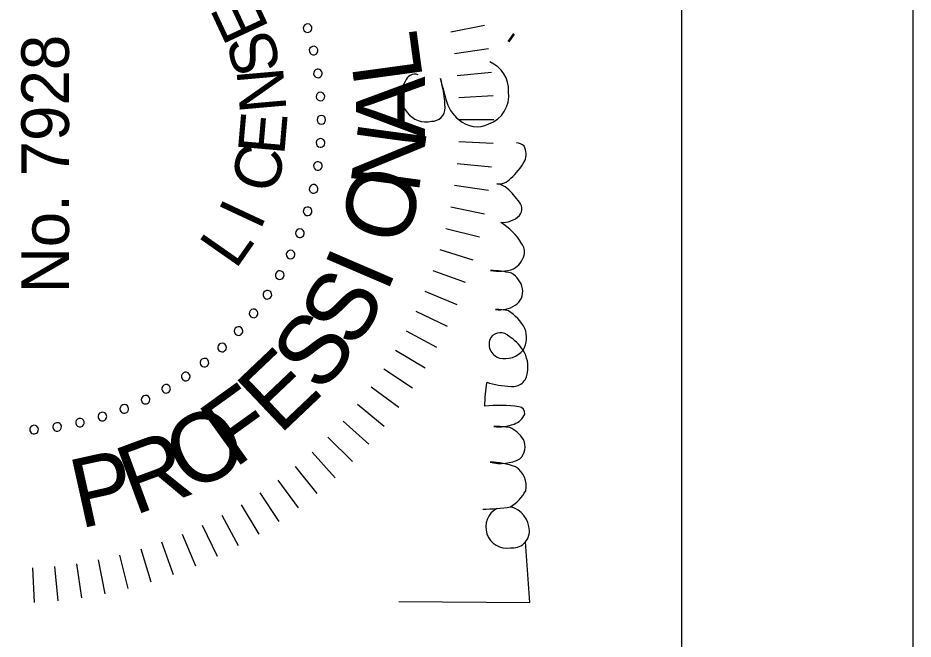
# Model space of a CAD drawing. Extents: x 916251 to 917164, y 328941 to 329491.
# Drawn here: x 917063.96 to 917100.87, y 329313.62 to 329339.21 of the extents above; entities that cross this region are included whole.
import ezdxf

# ---------------------------------------------------------------- set-up
doc = ezdxf.new("R2010")
doc.units = 0
for name, color, linetype in [('ANNOTATION', 7, 'Continuous'), ('Default', 7, 'Continuous'), ('elec-detail-ext-post-mtd-meter-panel', 7, 'Continuous')]:
    doc.layers.add(name, color=color, linetype=linetype)

# ---------------------------------------------------------------- blocks, each defined once
blk = doc.blocks.new('STAMP')
at = {"layer": 'Default'}
for p, q in [((-0.007955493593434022, 0.0011091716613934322), (-0.007387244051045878, 0.0011370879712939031)), ((-0.007926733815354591, 0.0007192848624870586), (-0.007360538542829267, 0.0007750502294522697)), ((-0.007878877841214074, 0.0003312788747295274), (-0.0073161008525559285, 0.00041475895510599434)), ((-0.007812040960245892, -5.391156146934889e-05), (-0.007254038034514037, 5.708212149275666e-05)), ((-0.0077263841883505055, -0.0004353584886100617), (-0.0071744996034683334, -0.00029711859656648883)), ((-0.007622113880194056, -0.0008121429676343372), (-0.007077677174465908, -0.0006469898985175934)), ((-0.00749948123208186, -0.0011833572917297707), (-0.0069638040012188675, -0.00099168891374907)), ((-0.007358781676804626, -0.0015481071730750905), (-0.006833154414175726, -0.001330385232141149)), ((-0.007200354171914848, -0.0019055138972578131), (-0.006686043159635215, -0.0016622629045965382)), ((-0.007024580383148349, -0.0022547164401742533), (-0.0065228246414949, -0.001986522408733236)), ((-0.006831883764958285, -0.002594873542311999), (-0.006343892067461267, -0.0023023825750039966)), ((-0.006622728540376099, -0.002925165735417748), (-0.0061496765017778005, -0.0026090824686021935)), ((-0.00639761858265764, -0.0032447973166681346), (-0.005940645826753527, -0.0029058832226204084)), ((-0.006157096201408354, -0.003552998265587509), (-0.005717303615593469, -0.0031920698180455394)), ((-0.005901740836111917, -0.003849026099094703), (-0.005480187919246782, -0.0034669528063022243)), ((-0.0056321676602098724, -0.0041321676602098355), (-0.00522986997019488, -0.003729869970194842)), ((-0.005349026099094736, -0.004401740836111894), (-0.004966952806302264, -0.003980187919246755)), ((-0.0050529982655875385, -0.004657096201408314), (-0.004692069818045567, -0.004217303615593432)), ((-0.004744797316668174, -0.0048976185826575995), (-0.004405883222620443, -0.004440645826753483)), ((-0.0044251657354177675, -0.005122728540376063), (-0.004109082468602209, -0.004649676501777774)), ((-0.004094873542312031, -0.005331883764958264), (-0.0038023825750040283, -0.004843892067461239)), ((-0.0037547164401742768, -0.005524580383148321), (-0.0034865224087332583, -0.005022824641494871)), ((-0.003405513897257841, -0.005700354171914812), (-0.0031622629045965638, -0.0051860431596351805)), ((-0.003048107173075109, -0.005858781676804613), (-0.0028303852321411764, -0.005333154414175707)), ((-0.0026833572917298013, -0.005999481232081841), (-0.002491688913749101, -0.005463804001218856)), ((-0.0023121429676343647, -0.006122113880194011), (-0.0021469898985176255, -0.005577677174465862)), ((-0.0019353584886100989, -0.006226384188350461), (-0.0017971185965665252, -0.005674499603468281)), ((-0.0015539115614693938, -0.006312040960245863), (-0.0014429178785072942, -0.005754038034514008)), ((0.0015539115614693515, -0.006312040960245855), (0.0014429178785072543, -0.005754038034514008)), ((-0.001168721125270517, -0.006378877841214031), (-0.0010852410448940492, -0.005816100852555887)), ((-0.0007807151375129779, -0.006426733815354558), (-0.0007249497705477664, -0.0058605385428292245)), ((-0.00039082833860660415, -0.006455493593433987), (-0.00036291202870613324, -0.005887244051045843)), ((-2.0539125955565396e-17, -0.006465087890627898), (-2.0539125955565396e-17, -0.005896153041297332)), ((0.0003908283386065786, -0.0064554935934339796), (0.0003629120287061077, -0.005887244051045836)), ((0.0007807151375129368, -0.006426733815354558), (0.0007249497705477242, -0.005860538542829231)), ((0.0011687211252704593, -0.006378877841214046), (0.0010852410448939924, -0.005816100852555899)), ((0.001282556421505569, -0.006716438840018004), (0.001411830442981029, -0.006805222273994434)), ((0.0012888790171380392, -0.0067038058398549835), (0.0014181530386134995, -0.006792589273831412))]:
    blk.add_line(p, q, dxfattribs=at)
blk.add_lwpolyline([(-0.007938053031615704, -0.004895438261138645), (-0.007956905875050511, -0.007061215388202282), (-0.0069577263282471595, -0.006985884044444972)], dxfattribs=at)
for centre, radius, start, end in [((-0.005106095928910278, 0.0011173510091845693), 7.111685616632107e-05, 94.28571428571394, 274.28571428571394), ((-0.005106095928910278, 0.0011173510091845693), 7.11168561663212e-05, 274.28571428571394, 94.28571428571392), ((-0.005063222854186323, 0.0007368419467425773), 7.111685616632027e-05, 98.5714285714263, 278.5714285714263), ((-0.005063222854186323, 0.0007368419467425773), 7.111685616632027e-05, 278.5714285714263, 98.5714285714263), ((-0.0049920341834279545, 0.00036060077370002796), 7.11168561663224e-05, 102.8571428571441, 282.8571428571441), ((-0.0049920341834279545, 0.00036060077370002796), 7.11168561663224e-05, 282.8571428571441, 102.85714285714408), ((-0.004892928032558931, -9.26841668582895e-06), 7.111685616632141e-05, 107.14285714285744, 287.14285714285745), ((-0.004892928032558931, -9.26841668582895e-06), 7.111685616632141e-05, 287.14285714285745, 107.14285714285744), ((-0.004766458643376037, -0.00037069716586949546), 7.111685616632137e-05, 111.42857142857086, 291.4285714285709), ((-0.004766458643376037, -0.00037069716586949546), 7.111685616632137e-05, 291.4285714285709, 111.42857142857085), ((-0.0046133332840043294, -0.0007216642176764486), 7.1116856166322e-05, 115.71428571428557, 295.71428571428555), ((-0.0046133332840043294, -0.0007216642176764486), 7.1116856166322e-05, 295.71428571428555, 115.71428571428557), ((-0.004434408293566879, -0.0010602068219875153), 7.111685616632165e-05, 119.99999999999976, 299.9999999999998), ((-0.004434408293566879, -0.0010602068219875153), 7.111685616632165e-05, 299.9999999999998, 119.99999999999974), ((-0.004230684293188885, -0.0013844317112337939), 7.111685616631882e-05, 124.28571428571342, 304.2857142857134), ((-0.004230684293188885, -0.0013844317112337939), 7.111685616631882e-05, 304.2857142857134, 124.28571428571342), ((-0.004003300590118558, -0.0016925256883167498), 7.111685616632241e-05, 308.5714285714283, 128.57142857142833), ((-0.004003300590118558, -0.0016925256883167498), 7.111685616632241e-05, 128.57142857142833, 308.5714285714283), ((-0.003753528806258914, -0.0019827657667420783), 7.11168561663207e-05, 312.85714285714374, 132.85714285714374), ((-0.003753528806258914, -0.0019827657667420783), 7.11168561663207e-05, 132.85714285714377, 312.8571428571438), ((-0.0034827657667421, -0.002253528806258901), 7.111685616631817e-05, 137.14285714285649, 317.1428571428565), ((-0.0034827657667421, -0.002253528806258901), 7.111685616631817e-05, 317.1428571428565, 137.14285714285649), ((-0.0031925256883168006, -0.0025033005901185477), 7.111685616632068e-05, 141.42857142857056, 321.42857142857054), ((-0.0031925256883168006, -0.0025033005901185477), 7.111685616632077e-05, 321.42857142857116, 141.4285714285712), ((-0.0028844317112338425, -0.0027306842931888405), 7.111685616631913e-05, 145.7142857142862, 325.71428571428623), ((-0.0028844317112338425, -0.0027306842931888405), 7.111685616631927e-05, 325.7142857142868, 145.71428571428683), ((-0.0025602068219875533, -0.0029344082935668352), 7.111685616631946e-05, 149.99999999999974, 329.9999999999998), ((-0.0025602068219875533, -0.0029344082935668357), 7.111685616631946e-05, 329.9999999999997, 149.99999999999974), ((-0.0022216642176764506, -0.0031133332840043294), 7.111685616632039e-05, 154.2857142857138, 334.28571428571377), ((-0.0022216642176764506, -0.0031133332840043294), 7.111685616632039e-05, 334.2857142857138, 154.2857142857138), ((-0.0018706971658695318, -0.003266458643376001), 7.111685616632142e-05, 158.57142857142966, 338.5714285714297), ((-0.0018706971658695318, -0.0032664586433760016), 7.111685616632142e-05, 338.57142857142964, 158.57142857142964), ((-0.0015092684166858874, -0.003392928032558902), 7.111685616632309e-05, 162.85714285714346, 342.85714285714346), ((-0.0015092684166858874, -0.003392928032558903), 7.111685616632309e-05, 342.85714285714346, 162.85714285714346), ((0.0015092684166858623, -0.0033929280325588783), 7.111685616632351e-05, 17.142857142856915, 197.1428571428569), ((0.0015092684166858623, -0.0033929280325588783), 7.111685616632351e-05, 197.1428571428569, 17.14285714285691), ((-0.0011393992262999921, -0.0034920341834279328), 7.111685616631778e-05, 167.14285714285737, 347.14285714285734), ((-0.0011393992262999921, -0.0034920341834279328), 7.111685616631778e-05, 347.14285714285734, 167.14285714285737), ((-0.0007631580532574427, -0.003563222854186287), 7.111685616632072e-05, 351.4285714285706, 171.4285714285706), ((-0.0003826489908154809, -0.003606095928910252), 7.111685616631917e-05, 355.7142857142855, 175.7142857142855), ((0.0003826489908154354, -0.0036060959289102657), 7.111685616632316e-05, 4.285714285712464, 184.28571428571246), ((0.0007631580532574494, -0.0035632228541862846), 7.111685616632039e-05, 8.571428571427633, 188.57142857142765), ((0.0011393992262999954, -0.0034920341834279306), 7.111685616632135e-05, 12.857142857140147, 192.85714285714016), ((0.0011393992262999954, -0.0034920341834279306), 7.111685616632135e-05, 192.85714285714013, 12.857142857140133), ((-0.0007631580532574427, -0.003563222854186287), 7.111685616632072e-05, 171.4285714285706, 351.4285714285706), ((-0.0003826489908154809, -0.003606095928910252), 7.111685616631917e-05, 175.71428571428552, 355.71428571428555), ((-1.2628786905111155e-17, -0.0036204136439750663), 7.111685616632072e-05, 0, 180), ((-1.2628786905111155e-17, -0.0036204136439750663), 7.111685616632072e-05, 180, 0), ((0.0003826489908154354, -0.0036060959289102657), 7.111685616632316e-05, 184.28571428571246, 4.285714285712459), ((0.0007631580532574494, -0.0035632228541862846), 7.111685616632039e-05, 188.57142857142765, 8.571428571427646), ((0.00039604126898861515, -0.005375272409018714), 0.00043958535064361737, 57.64755033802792, 128.97245422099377), ((0.0005805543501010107, -0.005165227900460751), 0.00016909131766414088, 342.3611945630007, 72.54487353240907), ((0.00036114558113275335, -0.0053488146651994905), 0.0003972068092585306, 127.45926190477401, 192.9614203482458), ((0.00019608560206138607, -0.005439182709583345), 0.0002220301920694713, 179.67057284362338, 269.694601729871), ((0.00015503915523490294, -0.003868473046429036), 0.001793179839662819, 271.2738092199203, 287.01217780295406), ((0.002166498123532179, -0.011827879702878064), 0.006419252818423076, 103.3923944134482, 106.55297850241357), ((0.0004564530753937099, -0.0062299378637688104), 0.0005678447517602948, 102.0773813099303, 143.39383108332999), ((0.00031613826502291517, -0.006186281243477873), 0.0004319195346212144, 136.9297266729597, 206.7934360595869), ((-0.00671307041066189, -0.006678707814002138), 0.0003465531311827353, 28.430349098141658, 189.68707560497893), ((-0.003955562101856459, -0.006312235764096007), 0.002461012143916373, 179.30402472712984, 190.0665804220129), ((-0.007015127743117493, -0.0065631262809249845), 0.0023079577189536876, 352.1195763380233, 6.249520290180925), ((-0.004786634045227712, -0.009314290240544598), 0.003003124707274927, 81.15725195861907, 88.74550427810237), ((-0.002857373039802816, -0.006810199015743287), 0.001539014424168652, 162.47862001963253, 177.5735090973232), ((-0.007040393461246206, -0.006369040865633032), 0.0013973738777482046, 341.03759348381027, 358.5906169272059), ((-0.004987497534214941, -0.006577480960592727), 0.0006786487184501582, 165.1377733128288, 207.96825790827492), ((-0.006329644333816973, -0.006519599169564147), 0.0012732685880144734, 350.5388137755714, 2.446920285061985), ((-0.004310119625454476, -0.006538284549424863), 0.0007509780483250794, 174.41813129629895, 200.30191948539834), ((-0.0037000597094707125, -0.006623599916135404), 0.00023723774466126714, 61.91684207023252, 163.66717131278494), ((-0.0037052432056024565, -0.0065716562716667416), 0.0001960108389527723, 312.7382758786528, 53.40100716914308), ((-0.003974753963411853, -0.006503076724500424), 0.0008496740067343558, 346.26214121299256, 0.7257075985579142), ((-0.002682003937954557, -0.006568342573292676), 0.00044961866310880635, 170.2648919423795, 213.2954708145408), ((-0.00388024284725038, -0.006412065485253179), 0.0013948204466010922, 345.72048696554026, 0.12433676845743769), ((-0.0016914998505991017, -0.006545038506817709), 0.0008054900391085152, 170.27954956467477, 197.78532003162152), ((0.0003962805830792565, -0.006217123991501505), 0.0004936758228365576, 199.38474076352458, 277.55079490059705), ((0.0004891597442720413, -0.006207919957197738), 0.0004993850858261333, 266.784921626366, 337.7362429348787), ((-0.0035430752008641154, -0.006644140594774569), 0.0003944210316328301, 167.2189950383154, 230.16055614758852), ((-0.002536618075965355, -0.006083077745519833), 0.0009765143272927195, 300.6803608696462, 329.51258202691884), ((-0.0012666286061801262, -0.006594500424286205), 0.00042878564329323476, 177.86300386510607, 223.17874837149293), ((-0.0013865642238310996, -0.006474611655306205), 0.0003320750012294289, 327.8843366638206, 353.1980671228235), ((-0.0008025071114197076, -0.006544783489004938), 0.0002561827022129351, 173.08541670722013, 230.55848375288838), ((-0.006777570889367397, -0.006772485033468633), 0.00027937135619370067, 172.70712454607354, 271.16395527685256), ((-0.006783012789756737, -0.006633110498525), 0.0004188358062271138, 271.5209447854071, 344.87406906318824), ((-0.005754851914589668, -0.006345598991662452), 0.0007393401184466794, 212.4592088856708, 240.63114206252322), ((-0.0055308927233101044, -0.006522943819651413), 0.0005014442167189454, 301.1133493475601, 335.74975916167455), ((-0.004152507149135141, -0.006775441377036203), 0.00024439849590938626, 172.85451562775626, 266.8151593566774), ((-0.00421927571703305, -0.006314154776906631), 0.0007614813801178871, 303.79189499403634, 328.18256979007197), ((-0.0038004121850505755, -0.006299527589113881), 0.000766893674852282, 298.0105046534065, 328.09350966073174), ((-0.00285343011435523, -0.006566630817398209), 0.0003761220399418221, 280.5798823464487, 329.7517392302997), ((-0.0020051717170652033, -0.0059200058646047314), 0.0011594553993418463, 305.5205731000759, 320.90595982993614), ((-0.0001785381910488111, -0.0060637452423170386), 0.0010391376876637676, 220.79179678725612, 241.16030041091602), ((-0.006036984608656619, -0.006622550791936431), 0.0003760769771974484, 257.6460165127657, 327.7710077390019), ((-0.005391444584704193, -0.006712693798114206), 0.0002677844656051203, 223.12676578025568, 296.5429712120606), ((-0.004715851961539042, -0.006689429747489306), 0.00031800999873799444, 200.1253724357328, 244.48124886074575), ((-0.004842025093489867, -0.006862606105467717), 0.00011432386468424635, 264.56536252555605, 351.47104640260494), ((-0.0028340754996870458, -0.006679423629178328), 0.00026169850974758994, 211.24435430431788, 280.94854976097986), ((-0.0021179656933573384, -0.00658432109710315), 0.00039838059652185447, 211.26450698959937, 253.32703764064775), ((-0.0021804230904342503, -0.006741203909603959), 0.00023065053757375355, 257.01114107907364, 308.02112433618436), ((-0.0014677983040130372, -0.006749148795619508), 0.0001780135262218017, 231.21384232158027, 319.94914487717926), ((-0.0005623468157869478, -0.006834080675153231), 0.00018159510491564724, 314.66347430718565, 358.2957841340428), ((-0.00407546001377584, -0.006500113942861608), 0.0005271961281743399, 260.1016649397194, 302.042575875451), ((-0.0035868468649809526, -0.00658750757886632), 0.00041578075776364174, 239.8376850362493, 290.64484911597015), ((-0.0005688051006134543, -0.006705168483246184), 0.00029083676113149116, 247.5695171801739, 297.4590386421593)]:
    blk.add_arc(centre, radius, start, end, dxfattribs=at)
for s, height, p in [('No. 7928', 0.0007851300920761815, (-0.002860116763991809, 0.0005420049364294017)), ('A', 0.0011378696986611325, (-0.0003007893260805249, -0.005327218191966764))]:
    blk.add_text(s, height=height, dxfattribs=at).set_placement(p)
for s, height, rotation, p in [('P', 0.0011378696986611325, 282.5, (-0.006741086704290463, 0.00036378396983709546)), ('R', 0.0011378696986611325, 290.25, (-0.00652629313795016, -0.0005348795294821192)), ('O', 0.0011378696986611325, 298, (-0.006169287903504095, -0.0014396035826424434)), ('F', 0.001137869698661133, 305.75, (-0.0057573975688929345, -0.002187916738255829)), ('L', 0.0007680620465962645, 324.99999999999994, (-0.002479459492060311, -0.00220631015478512)), ('E', 0.0007680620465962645, 25.000000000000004, (0.001513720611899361, -0.002766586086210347)), ('I', 0.0007680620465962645, 335, (-0.001841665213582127, -0.002604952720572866)), ('C', 0.0007680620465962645, 345, (-0.0012469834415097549, -0.0028524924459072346)), ('S', 0.0007680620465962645, 14.999999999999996, (0.0008506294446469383, -0.0029637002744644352)), ('E', 0.0011378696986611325, 313.5, (-0.005207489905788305, -0.0029306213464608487)), ('E', 0.0007680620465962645, 355, (-0.0005969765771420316, -0.00300722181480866)), ('N', 0.0007680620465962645, 5, (0.0001499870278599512, -0.003047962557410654)), ('S', 0.0011378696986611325, 321.25, (-0.004535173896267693, -0.0036142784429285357)), ('S', 0.0011378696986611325, 328.99999999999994, (-0.003804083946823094, -0.004179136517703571)), ('I', 0.0011378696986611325, 336.75, (-0.0028749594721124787, -0.00469547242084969)), ('O', 0.001137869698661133, 344.5, (-0.0021143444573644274, -0.004998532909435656)), ('N', 0.001137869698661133, 352.25, (-0.001239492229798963, -0.005221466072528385)), ('L', 0.001137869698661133, 7.75, (0.0006711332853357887, -0.0052988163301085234))]:
    blk.add_text(s, height=height, rotation=rotation, dxfattribs=at).set_placement(p)

msp = doc.modelspace()

# ---------------------------------------------------------------- linework, layer by layer
at = {"layer": 'ANNOTATION'}
msp.add_lwpolyline([(916250.8701015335, 328941.0840016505), (917100.8684015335, 328941.0840016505), (917100.8684015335, 329491.0829016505), (916250.8701015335, 329491.0829016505)], close=True, dxfattribs=at)
at = {"layer": 'elec-detail-ext-post-mtd-meter-panel'}
msp.add_line((917091.3351521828, 328956.39453486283), (917091.3351521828, 329481.3934848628), dxfattribs=at)

# ---------------------------------------------------------------- block references
at = {"layer": 'elec-detail-ext-post-mtd-meter-panel', "xscale": 2499.999999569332, "yscale": 2499.999999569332, "rotation": 90}
msp.add_blockref('STAMP', (917067.4209062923, 329335.01261332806), dxfattribs=at)

doc.saveas('drawing.dxf')
